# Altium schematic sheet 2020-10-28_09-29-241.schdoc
size 378 x 133 mm; SheetNumber: 1; SheetTotal: 1
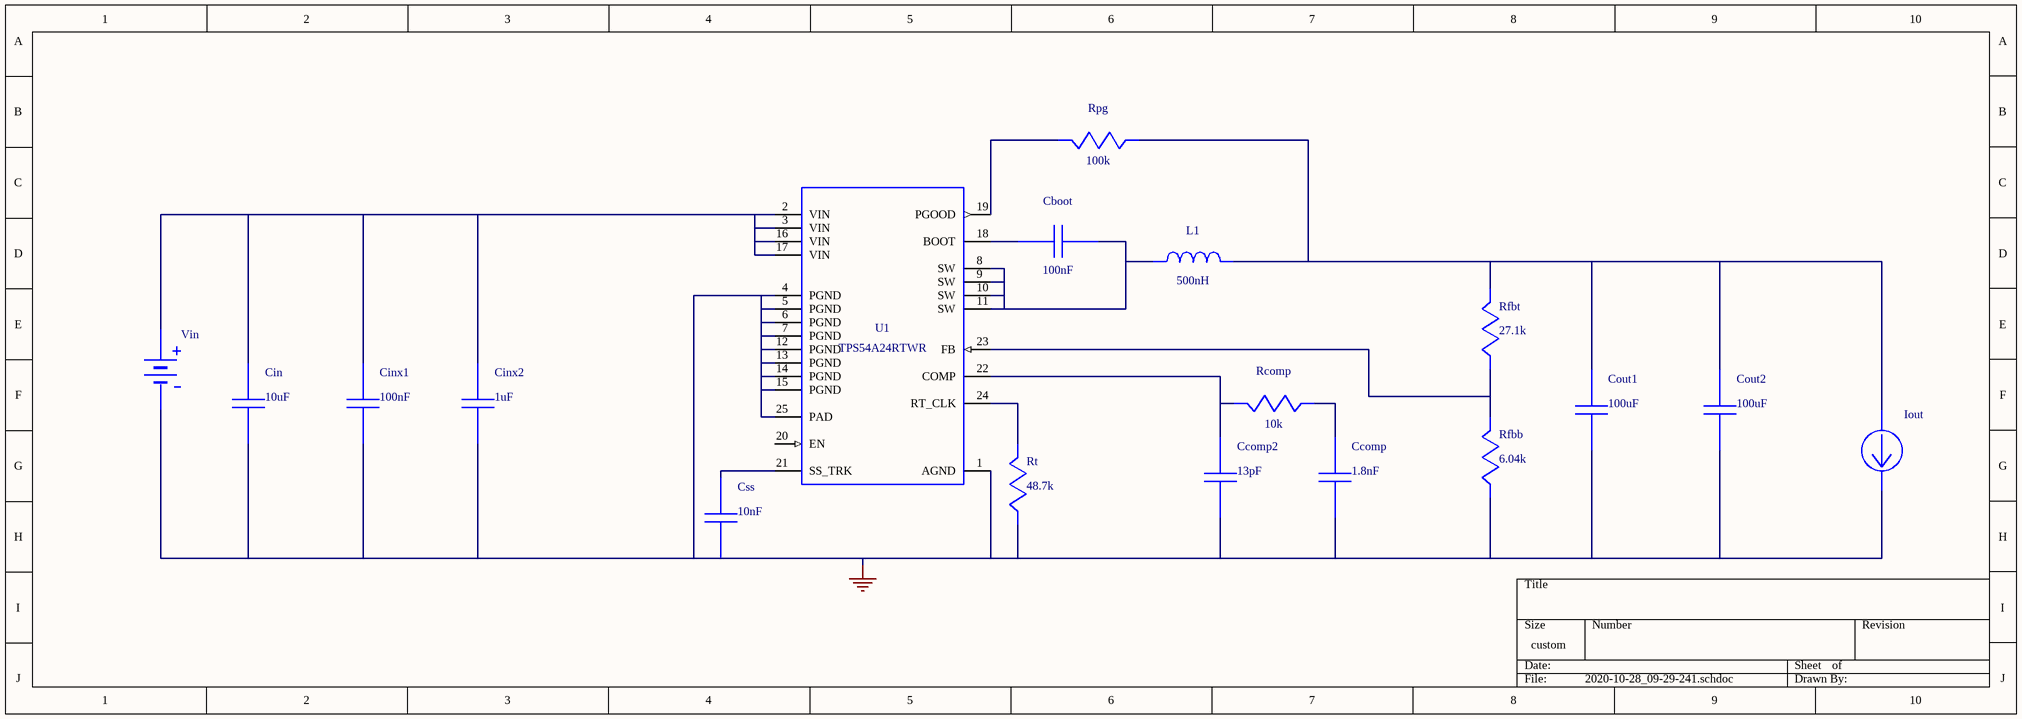
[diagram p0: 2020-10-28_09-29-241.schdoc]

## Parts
Cboot  value 100nF  (hidden comment: GRM155R71C104KA88D)
Ccomp  value 1.8nF  (hidden comment: GRM1885C1H182JA01J)
Ccomp2  value 13pF  (hidden comment: CL05C130JB5NNNC)
Cin  value 10uF  (hidden comment: C0805C106K8PACTU)
Cinx1  value 100nF  (hidden comment: GRM188R71H104KA93D)
Cinx2  value 1uF  (hidden comment: C1608X7R1H472K)
Cout1  value 100uF  (hidden comment: GRM31CR60J107ME39L)
Cout2  value 100uF  (hidden comment: GRM31CR60J107ME39L)
Css  value 10nF  (hidden comment: GRM155R61A103KA01D)
Iout  WB_CURRENT_LOAD  (value not drawn)
L1  value 500nH  (hidden comment: SRN8040-R50Y)
Rcomp  value 10k  (hidden comment: CRCW040210K0FKED)
Rfbb  value 6.04k  (hidden comment: CRCW04026K04FKED)
Rfbt  value 27.1k  (hidden comment: RT0805BRD0727K1L)
Rpg  value 100k  (hidden comment: CRCW0402100KFKED)
Rt  value 48.7k  (hidden comment: CRCW040248K7FKED)
U1  TPS54A24RTWR
Vin  WB_BATTERY  (value not drawn)

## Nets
0: Ccomp.1 Ccomp2.1 Cin.2 Cinx1.2 Cinx2.2 Cout1.2 Cout2.2 Css.2 Iout.2(-) Rfbb.2 Rt.2 U1.1(AGND) U1.4(PGND) U1.5(PGND) U1.6(PGND) U1.7(PGND) U1.12(PGND) U1.13(PGND) U1.14(PGND) U1.15(PGND) U1.25(PAD) Vin.2(-)
NetCboot_1: Cboot.1 U1.18(BOOT)
NetCboot_2: Cboot.2 L1.2 U1.8(SW) U1.9(SW) U1.10(SW) U1.11(SW)
NetCcomp2_2: Ccomp2.2 Rcomp.1 U1.22(COMP)
NetCcomp_2: Ccomp.2 Rcomp.2
NetCin_1: Cin.1 Cinx1.1 Cinx2.1 U1.2(VIN) U1.3(VIN) U1.16(VIN) U1.17(VIN) Vin.1(+)
NetCout1_1: Cout1.1 Cout2.1 Iout.1(+) L1.1 Rfbt.1 Rpg.2
NetCss_1: Css.1 U1.21(SS_TRK)
NetRfbb_1: Rfbb.1 Rfbt.2 U1.23(FB)
NetRpg_1: Rpg.1 U1.19(PGOOD)
NetRt_1: Rt.1 U1.24(RT_CLK)

Not connected (* = marked no-connect by the designer): U1 20(EN)

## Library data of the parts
Cboot = GRM155R71C104KA88D: GRM155R71C104KA8; Manufacturer Name: MuRata
Ccomp = GRM1885C1H182JA01J: GRM1885C1H182JA0; Manufacturer Name: MuRata
Ccomp2 = CL05C130JB5NNNC: Manufacturer Name: Samsung Electro-Mechanics
Cin = C0805C106K8PACTU: Manufacturer Name: Kemet
Cinx1 = GRM188R71H104KA93D: GRM188R71H104KA9; Manufacturer Name: MuRata
Cinx2 = C1608X7R1H472K: C1608X7R1V105K08; Manufacturer Name: TDK
Cout1 Cout2 = GRM31CR60J107ME39L: GRM31CR60J107ME3; Manufacturer Name: MuRata
Css = GRM155R61A103KA01D: GRM155R61A103KA0; Manufacturer Name: MuRata
L1 = SRN8040-R50Y: Manufacturer Name: Bourns
Rcomp = CRCW040210K0FKED: Manufacturer Name: Vishay-Dale
Rfbb = CRCW04026K04FKED: Manufacturer Name: Vishay-Dale
Rfbt = RT0805BRD0727K1L: Manufacturer Name: Yageo
Rpg = CRCW0402100KFKED: Manufacturer Name: Vishay-Dale
Rt = CRCW040248K7FKED: Manufacturer Name: Vishay-Dale
U1 = TPS54A24RTWR: Manufacturer Name: Texas Instruments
